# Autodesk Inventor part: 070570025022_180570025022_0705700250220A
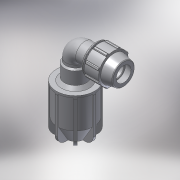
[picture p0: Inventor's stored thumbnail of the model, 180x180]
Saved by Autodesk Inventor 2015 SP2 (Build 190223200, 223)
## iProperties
Created: 2017-02
Part Number: 070570025022_180570025022_0705700250220A
Material: PVC-Piping
Description: PLASSON PLASS4 90° ELBOW 15-22*25
Document SubType Name: Modeling
Designer: KIM
Mass: 92.6774 g
Surface Area: 199.44 cm^2
Volume: 66.1981 cm^3
Density: 1.4 g/cm^3
Appearance: Smooth - White
Author: KIM
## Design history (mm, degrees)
derived "070570.ipt"
feature "Solid1::070570.ipt"
tag "TaggingFeature1"
body "Solid1"
other parameters: "d2" = 25, "d4" = 11.57143, "d5" = 16.2, "d7" = 54, "d8" = 31.55097, "d9" = 11.57143, "d11" = 2.31429, "d12" = 43.2, "d13" = 120 deg, "d14" = 37.5, "d15" = 12 deg, "d16" = 48.6, "d18" = 1.25, "d19" = 35 deg, "d20" = 17.5 deg, "d21" = 50.22, "d23" = 0, "d25" = 360 deg, "d27" = 1.08, "d42" = 24.3, "d43" = 1.62, "d46" = 0.75, "d53" = 0.5, "d67" = 2.7, "d70" = 22.5, "d71" = 58, "d73" = 81, "d74" = 90 deg, "d75" = 22, "d76" = 64, "d77" = 128, "d78" = 4.05, "d80" = 22.5, "d82" = 105, "d84" = 60.8, "d85" = 135 deg, "d86" = 3.2, "d88" = 105, "d89" = 3.2, "d90" = 135 deg, "d91" = 78.75, "d92" = 20.48, "d93" = 26.25, "d94" = 3.2, "d95" = 5.25, "d97" = 4.32, "d98" = 0, "d100" = 360 deg, "d102" = 70.4, "d103" = 12.8, "d104" = 5.12, "d105" = 0, "d107" = 16.2, "d108" = 0, "d109" = 0, "d_" = 25, "E_" = 54, "A_" = 81, "l_" = 58, "d_1" = 22, "E_1" = 64, "l_1" = 105, "A_1" = 128, "d106" = 31.55097
